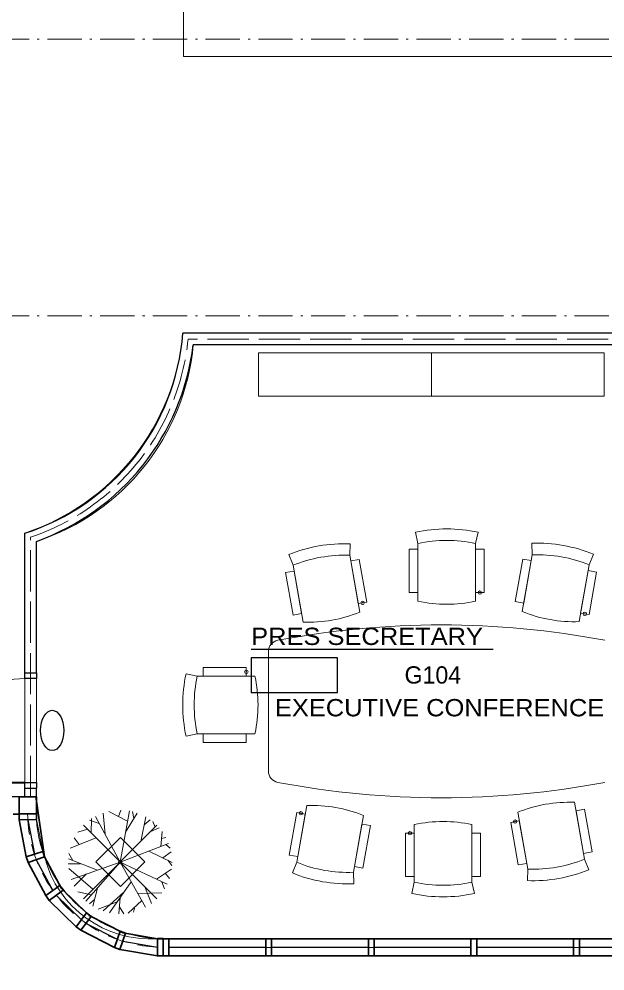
# Model space of a CAD drawing. Extents: x -118748 to -117136, y -118748 to -117596.
# Drawn here: x -117888.7 to -117726.1, y -118597 to -118332.8 of the extents above; entities that cross this region are included whole.
import ezdxf
from ezdxf.enums import TextEntityAlignment as Align

# ---------------------------------------------------------------- set-up
doc = ezdxf.new("R2010")
doc.units = 0
doc.header["$LTSCALE"] = 1.9
doc.header["$PDMODE"] = 32
doc.header["$PDSIZE"] = 0.95
for name, pattern in [('DOT_DASHED', [7.7, 5, -1.2, 0.3, -1.2]), ('LONG_DASHED', [7.5, 6, -1.5]), ('MEDIUM_DASHED', [4.5, 3, -1.5])]:
    doc.linetypes.add(name, pattern=pattern)
for name, color, linetype, lineweight in [('10', 7, 'DOT_DASHED', 13), ('15', 7, 'Continuous', 13), ('17', 7, 'Continuous', 25), ('2', 7, 'Continuous', 35), ('23', 7, 'Continuous', 25), ('25', 7, 'Continuous', 13), ('26', 7, 'Continuous', 25), ('3', 7, 'Continuous', 35), ('30', 7, 'Continuous', 13), ('4', 7, 'Continuous', 35), ('42', 7, 'Continuous', 25), ('45', 7, 'Continuous', 25), ('5', 7, 'Continuous', 13), ('6', 7, 'Continuous', 13), ('60', 7, 'LONG_DASHED', 13), ('8', 7, 'MEDIUM_DASHED', 13), ('9', 7, 'Continuous', 35)]:
    doc.layers.add(name, color=color, linetype=linetype, lineweight=lineweight)
doc.layers.add('53', color=7, linetype='Continuous')

msp = doc.modelspace()

# ---------------------------------------------------------------- linework, layer by layer
at = {"layer": '10'}
for p, q in [((-118641.571, -118338.41), (-117285.521, -118338.41)), ((-118641.571, -118415.21), (-117285.521, -118415.21))]:
    msp.add_line(p, q, dxfattribs=at)
at = {"layer": '15'}
for p, q in [((-117778.001, -118478.357), (-117778.677, -118475.23)), ((-117762.001, -118478.357), (-117761.325, -118475.23)), ((-117796.908, -118481.624), (-117796.786, -118478.427)), ((-117778.001, -118494.357), (-117778.001, -118478.357)), ((-117762.001, -118494.357), (-117762.001, -118478.357)), ((-117746.253, -118481.492), (-117746.376, -118478.294)), ((-117812.665, -118484.403), (-117813.874, -118481.44)), ((-117794.13, -118497.381), (-117796.908, -118481.624)), ((-117780.401, -118491.957), (-117780.401, -118479.957)), ((-117778.001, -118479.957), (-117780.401, -118479.957)), ((-117778.001, -118491.957), (-117778.001, -118479.957)), ((-117762.001, -118491.957), (-117762.001, -118479.957)), ((-117759.601, -118479.957), (-117762.001, -118479.957)), ((-117759.601, -118491.957), (-117759.601, -118479.957)), ((-117749.031, -118497.249), (-117746.253, -118481.492)), ((-117730.496, -118484.27), (-117729.287, -118481.307)), ((-117794.267, -118482.783), (-117796.63, -118483.2)), ((-117794.547, -118495.018), (-117796.63, -118483.2)), ((-117792.183, -118494.601), (-117794.267, -118482.783)), ((-117750.978, -118494.469), (-117748.894, -118482.651)), ((-117746.531, -118483.068), (-117748.894, -118482.651)), ((-117748.615, -118494.885), (-117746.531, -118483.068)), ((-117733.274, -118500.027), (-117730.496, -118484.27)), ((-117812.387, -118485.978), (-117814.751, -118486.395)), ((-117812.667, -118498.213), (-117814.751, -118486.395)), ((-117809.887, -118500.16), (-117812.665, -118484.403)), ((-117810.304, -118497.796), (-117812.387, -118485.978)), ((-117732.858, -118497.664), (-117730.774, -118485.846)), ((-117728.41, -118486.263), (-117730.774, -118485.846)), ((-117730.494, -118498.08), (-117728.41, -118486.263)), ((-117780.401, -118491.957), (-117778.001, -118491.957)), ((-117762.001, -118491.957), (-117759.601, -118491.957)), ((-117794.547, -118495.018), (-117792.183, -118494.601)), ((-117750.978, -118494.469), (-117748.615, -118494.885)), ((-117812.667, -118498.213), (-117810.304, -118497.796)), ((-117732.858, -118497.664), (-117730.494, -118498.08)), ((-117819.492, -118541.486), (-117819.492, -118508.352)), ((-117825.635, -118512.747), (-117837.635, -118512.747)), ((-117837.635, -118512.747), (-117837.635, -118515.147)), ((-117825.635, -118515.147), (-117825.635, -118512.747)), ((-117839.235, -118515.147), (-117842.362, -118514.47)), ((-117823.235, -118515.147), (-117839.235, -118515.147)), ((-117825.635, -118515.147), (-117837.635, -118515.147)), ((-117839.235, -118531.147), (-117842.362, -118531.823)), ((-117823.235, -118531.147), (-117839.235, -118531.147)), ((-117825.635, -118531.147), (-117837.635, -118531.147)), ((-117837.635, -118531.147), (-117837.635, -118533.547)), ((-117825.635, -118533.547), (-117825.635, -118531.147)), ((-117825.635, -118533.547), (-117837.635, -118533.547)), ((-117734.527, -118550.167), (-117731.748, -118565.924)), ((-117811.652, -118553.002), (-117813.735, -118564.82)), ((-117809.288, -118553.418), (-117811.652, -118553.002)), ((-117808.871, -118551.055), (-117811.65, -118566.812)), ((-117750.284, -118552.945), (-117747.505, -118568.702)), ((-117731.747, -118552.113), (-117734.11, -118552.53)), ((-117734.11, -118552.53), (-117732.026, -118564.348)), ((-117731.747, -118552.113), (-117729.663, -118563.931)), ((-117809.288, -118553.418), (-117811.372, -118565.236)), ((-117793.114, -118553.833), (-117795.893, -118569.59)), ((-117749.867, -118555.308), (-117752.231, -118555.725)), ((-117749.867, -118555.308), (-117747.783, -118567.126)), ((-117793.531, -118556.197), (-117795.615, -118568.015)), ((-117791.168, -118556.614), (-117793.531, -118556.197)), ((-117791.168, -118556.614), (-117793.251, -118568.431)), ((-117779.011, -118556.347), (-117779.011, -118572.347)), ((-117763.011, -118556.347), (-117763.011, -118572.347)), ((-117752.231, -118555.725), (-117750.147, -118567.543)), ((-117781.411, -118558.747), (-117781.411, -118570.747)), ((-117779.011, -118558.747), (-117781.411, -118558.747)), ((-117779.011, -118558.747), (-117779.011, -118570.747)), ((-117763.011, -118558.747), (-117763.011, -118570.747)), ((-117760.611, -118558.747), (-117763.011, -118558.747)), ((-117760.611, -118558.747), (-117760.611, -118570.747)), ((-117813.735, -118564.82), (-117811.372, -118565.236)), ((-117732.026, -118564.348), (-117729.663, -118563.931)), ((-117731.748, -118565.924), (-117730.539, -118568.886)), ((-117811.65, -118566.812), (-117812.859, -118569.775)), ((-117795.615, -118568.015), (-117793.251, -118568.431)), ((-117750.147, -118567.543), (-117747.783, -118567.126)), ((-117747.505, -118568.702), (-117747.628, -118571.899)), ((-117795.893, -118569.59), (-117795.77, -118572.788)), ((-117781.411, -118570.747), (-117779.011, -118570.747)), ((-117763.011, -118570.747), (-117760.611, -118570.747)), ((-117779.011, -118572.347), (-117779.687, -118575.475)), ((-117763.011, -118572.347), (-117762.334, -118575.475))]:
    msp.add_line(p, q, dxfattribs=at)
for points in [[(-117774.28, -118425.478), (-117774.28, -118437.478), (-117822.28, -118437.478), (-117822.28, -118425.478)], [(-117726.28, -118425.478), (-117726.28, -118437.478), (-117774.28, -118437.478), (-117774.28, -118425.478)]]:
    msp.add_lwpolyline(points, close=True, dxfattribs=at)
for centre, radius, start, end in [((-117770.001, -118515.366), 41.063, 77.80217, 102.19783), ((-117798.36, -118519.46), 41.063, 87.80217, 112.19782), ((-117770.001, -118515.366), 37.863, 77.80217, 102.19783), ((-117770.001, -118515.366), 37.863, 77.80217, 102.19783), ((-117744.801, -118519.327), 41.063, 67.80217, 92.19783), ((-117798.36, -118519.46), 37.863, 87.80217, 112.19782), ((-117798.36, -118519.46), 37.863, 87.80217, 112.19782), ((-117744.801, -118519.327), 37.863, 67.80217, 92.19783), ((-117744.801, -118519.327), 37.863, 67.80217, 92.19783), ((-117770.001, -118457.349), 37.863, 257.80217, 282.19783), ((-117808.435, -118462.324), 37.863, 267.80217, 292.19782), ((-117734.727, -118462.192), 37.863, 247.80217, 272.19783), ((-117771.492, -118743.319), 242.4, 79.20527, 100.79473), ((-117816.292, -118508.351), 3.2, 100.79473, 180), ((-117802.226, -118523.147), 41.063, 167.80217, 192.19782), ((-117802.226, -118523.147), 37.863, 167.80217, 192.19782), ((-117802.226, -118523.147), 37.863, 167.80217, 192.19782), ((-117860.243, -118523.147), 37.863, 347.80217, 12.19783), ((-117816.292, -118541.486), 3.2, 180, 259.20527), ((-117771.492, -118306.519), 242.4, 259.20527, 280.79473), ((-117735.979, -118588.002), 37.863, 87.80216, 112.19782), ((-117807.419, -118588.89), 37.863, 67.80217, 92.19782), ((-117771.011, -118593.355), 37.863, 77.80217, 102.19783), ((-117746.053, -118530.867), 37.863, 267.80217, 292.19783), ((-117746.053, -118530.867), 37.863, 267.80217, 292.19783), ((-117797.345, -118531.755), 37.863, 247.80217, 272.19783), ((-117797.345, -118531.755), 37.863, 247.80217, 272.19783), ((-117797.345, -118531.755), 41.063, 247.80217, 272.19783), ((-117746.053, -118530.867), 41.063, 267.80217, 292.19783), ((-117771.011, -118535.339), 37.863, 257.80217, 282.19783), ((-117771.011, -118535.339), 37.863, 257.80217, 282.19783), ((-117771.011, -118535.339), 41.063, 257.80217, 282.19783)]:
    msp.add_arc(centre, radius, start, end, dxfattribs=at)
for p in [(-117760.801, -118491.957), (-117793.365, -118494.809), (-117731.676, -118497.872), (-117825.635, -118513.947), (-117810.47, -118553.21), (-117751.049, -118555.517), (-117780.211, -118558.747)]:
    msp.add_point(p, dxfattribs=at)
at = {"layer": '17'}
msp.add_line((-117824.295, -118507.709), (-117757.095, -118507.709), dxfattribs=at)
at = {"layer": '2'}
msp.add_lwpolyline([(-117888.716, -118548.633), (-117888.716, -118553.358), (-117883.908, -118553.358), (-117883.908, -118548.633)], close=True, dxfattribs=at)
at = {"layer": '23'}
for p, q in [((-117698.321, -118420.01), (-117843.25, -118420.01)), ((-117698.321, -118423.21), (-117840.35, -118423.21)), ((-117887.108, -118514.233), (-117887.108, -118475.475)), ((-117883.908, -118514.233), (-117883.908, -118477.77)), ((-117887.108, -118514.233), (-117883.908, -118514.233)), ((-117887.108, -118546.233), (-117883.908, -118546.233)), ((-117887.108, -118548.633), (-117887.108, -118546.233)), ((-117883.908, -118548.633), (-117883.908, -118546.233)), ((-117887.108, -118548.633), (-117883.908, -118548.633))]:
    msp.add_line(p, q, dxfattribs=at)
for radius, start, end in [(63.254, 287.68267, 355.64793), (66.454, 289.71078, 353.08572)]:
    msp.add_arc((-117906.321, -118415.21), radius, start, end, dxfattribs=at)
at = {"layer": '25', "lineweight": 40}
msp.add_line((-117915.908, -118544.633), (-117887.108, -118544.633), dxfattribs=at)
at = {"layer": '25'}
msp.add_arc((-117887.108, -118544.633), 28.8, 90.00001, 180, dxfattribs=at)
at = {"layer": '26'}
for points in [[(-117883.908, -118514.233), (-117883.908, -118515.833), (-117887.108, -118515.833), (-117887.108, -118514.233)], [(-117887.108, -118546.233), (-117887.108, -118544.633), (-117883.908, -118544.633), (-117883.908, -118546.233)]]:
    msp.add_lwpolyline(points, dxfattribs=at)
at = {"layer": '3'}
msp.add_lwpolyline([(-118098.321, -117954.41), (-117829.521, -117954.41), (-117459.921, -117954.41), (-117459.921, -118170.41), (-117370.321, -118170.41), (-117370.321, -118352.81), (-117459.921, -118352.81), (-117459.921, -118645.61), (-117704.721, -118645.61), (-117704.721, -118592.81), (-117847.121, -118592.81), (-117850.321, -118592.801), (-117860.744, -118590.984), (-117862.249, -118590.443), (-117871.571, -118585.668), (-117872.847, -118584.703), (-117880.323, -118577.368), (-117881.254, -118576.067), (-117886.205, -118566.837), (-117886.706, -118565.318), (-117888.682, -118555.032), (-117888.707, -118553.433), (-117890.316, -118553.433)], dxfattribs=at)
at = {"layer": '30'}
for p, q in [((-117858.58, -118555.405), (-117863.781, -118552.673)), ((-117861.071, -118554.096), (-117860.479, -118552.331)), ((-117860.655, -118566.73), (-117858.059, -118552.566)), ((-117856.841, -118554.677), (-117857.251, -118552.738)), ((-117866.438, -118556.086), (-117869.12, -118555.081)), ((-117868.718, -118558.667), (-117868.571, -118554.701)), ((-117860.655, -118566.73), (-117867.529, -118554.077)), ((-117864.852, -118559.004), (-117865.392, -118553.132)), ((-117859.135, -118558.439), (-117855.901, -118553.137)), ((-117854.95, -118561.025), (-117853.513, -118554.226)), ((-117853.975, -118556.41), (-117852.309, -118554.995)), ((-117850.944, -118557.019), (-117851.6, -118555.533)), ((-117869.732, -118557.653), (-117872.414, -118558.418)), ((-117850.472, -118556.548), (-117870.837, -118576.912)), ((-117850.472, -118576.912), (-117870.837, -118556.548)), ((-117852.161, -118558.236), (-117849.832, -118557.231)), ((-117849.332, -118562.428), (-117848.988, -118558.289)), ((-117867.323, -118560.061), (-117874.535, -118562.897)), ((-117871.991, -118561.897), (-117873.4, -118560.027)), ((-117849.148, -118560.215), (-117847.965, -118559.924)), ((-117860.655, -118566.73), (-117847.194, -118561.615)), ((-117847.99, -118561.918), (-117846.764, -118562.932)), ((-117866.978, -118568.978), (-117875.029, -118565.875)), ((-117873.789, -118566.353), (-117874.857, -118564.35)), ((-117852.724, -118563.717), (-117846.255, -118566.831)), ((-117848.805, -118565.603), (-117846.53, -118563.925)), ((-117871.607, -118567.194), (-117875.044, -118567.284)), ((-117868.236, -118574.311), (-117874.936, -118568.573)), ((-117860.655, -118566.73), (-117874.223, -118571.554)), ((-117860.655, -118566.73), (-117870.13, -118577.573)), ((-117860.655, -118566.73), (-117853.609, -118579.289)), ((-117860.655, -118566.73), (-117847.622, -118572.855)), ((-117850.602, -118571.455), (-117846.391, -118568.709)), ((-117847.429, -118566.266), (-117846.285, -118567.668)), ((-117869.982, -118570.046), (-117873.387, -118573.456)), ((-117848.172, -118569.87), (-117846.994, -118571.284)), ((-117866.977, -118573.965), (-117868.245, -118578.967)), ((-117857.566, -118572.236), (-117863.641, -118580.817)), ((-117853.809, -118573.576), (-117851.986, -118578.229)), ((-117849.043, -118572.187), (-117848.325, -118574.168)), ((-117868.577, -118575.797), (-117872.427, -118575.022)), ((-117859.597, -118575.105), (-117865.406, -118580.323)), ((-117860.667, -118576.617), (-117860.993, -118581.126)), ((-117855.755, -118575.463), (-117849.07, -118575.283)), ((-117867.784, -118577.149), (-117869.199, -118578.321)), ((-117861.505, -118577.8), (-117866.704, -118579.798)), ((-117860.851, -118579.163), (-117859.663, -118581.096)), ((-117854.654, -118577.427), (-117858.446, -118580.959)), ((-117856.554, -118579.197), (-117856.955, -118580.647))]:
    msp.add_line(p, q, dxfattribs=at)
msp.add_lwpolyline([(-117853.802, -118566.727), (-117860.59, -118573.515), (-117867.378, -118566.727), (-117860.59, -118559.938)], close=True, dxfattribs=at)
msp.add_point((-117860.655, -118566.73), dxfattribs=at)
at = {"layer": '4'}
msp.add_lwpolyline([(-118496.721, -117964.01), (-118496.721, -118636.01), (-118271.121, -118636.01), (-118271.121, -118588.01), (-118115.969, -118588.01), (-118106.1, -118586.234), (-118096.66, -118581.314), (-118089.115, -118573.804), (-118084.156, -118564.399), (-118081.154, -118548.633), (-118079.134, -118548.633), (-117884.057, -118548.587), (-117881.646, -118565.336), (-117876.897, -118574.111), (-117869.271, -118581.538), (-117859.789, -118586.351), (-117850.271, -118588.01), (-117695.121, -118588.01), (-117695.121, -118636.01), (-117469.521, -118636.01), (-117469.521, -117964.01)], close=True, dxfattribs=at)
at = {"layer": '42'}
msp.add_ellipse((-117879.508, -118530.233), major_axis=(0, -5.6), ratio=0.571429, dxfattribs=at)
at = {"layer": '45'}
msp.add_lwpolyline([(-117824.295, -118510.109), (-117824.295, -118519.709), (-117800.295, -118519.709), (-117800.295, -118510.109)], close=True, dxfattribs=at)
at = {"layer": '5'}
for points in [[(-117979.078, -117964.01), (-117469.521, -117964.01), (-117469.521, -118636.01), (-117695.121, -118636.01), (-117695.121, -118588.01), (-117850.271, -118588.01)], [(-117843.071, -118184.81), (-117843.071, -118295.21), (-117503.121, -118295.21), (-117469.521, -118295.21), (-117469.521, -118301.61), (-117469.521, -118343.21), (-117479.121, -118343.21), (-117698.321, -118343.21), (-117698.321, -118357.61), (-117698.321, -118420.01), (-117843.25, -118420.01)], [(-117840.35, -118423.21), (-117666.321, -118423.21), (-117666.321, -118456.81), (-117666.321, -118588.01), (-117706.321, -118588.01), (-117847.121, -118588.01), (-117850.321, -118588.001), (-117859.12, -118586.467), (-117860.626, -118585.926), (-117868.676, -118581.84), (-117869.952, -118580.875), (-117876.419, -118574.577), (-117877.349, -118573.275), (-117881.646, -118565.336), (-117882.147, -118563.816), (-117883.883, -118554.958), (-117883.908, -118477.769)], [(-117887.108, -118475.475), (-117887.108, -118548.633), (-118079.134, -118548.633), (-118079.133, -118475.475)], [(-117881.646, -118565.336), (-117884.057, -118548.587), (-118079.134, -118548.633), (-118081.154, -118548.633), (-118084.156, -118564.399)]]:
    msp.add_lwpolyline(points, dxfattribs=at)
for centre, radius, start, end in [((-117906.321, -118415.21), 63.254, 287.68267, 355.64793), ((-117906.321, -118415.21), 66.454, 289.71078, 353.08572), ((-117852.266, -118557.725), 30.35, 194.52311, 273.7691)]:
    msp.add_arc(centre, radius, start, end, dxfattribs=at)
at = {"layer": '6'}
msp.add_line((-117883.908, -118477.77), (-117883.883, -118554.958), dxfattribs=at)
for points in [[(-117843.071, -118184.81), (-117843.071, -118343.21), (-117698.321, -118343.21), (-117698.321, -118420.01), (-117843.25, -118420.01)], [(-117850.321, -118588.001), (-117695.121, -118588.01), (-117695.121, -118636.01), (-117469.521, -118636.01), (-117469.521, -118423.21), (-117840.35, -118423.21)], [(-117887.108, -118475.475), (-117887.108, -118548.633), (-118079.134, -118548.633), (-118079.134, -118475.475)]]:
    msp.add_lwpolyline(points, dxfattribs=at)
msp.add_lwpolyline([(-117843.071, -118295.21), (-117469.521, -118295.21), (-117469.521, -118343.21), (-117843.071, -118343.21)], close=True, dxfattribs=at)
for centre, radius, start, end in [((-117907.46, -118414.309), 64.463, 288.40401, 354.92664), ((-117903.662, -118417.332), 63.584, 288.09981, 354.69642), ((-117848.402, -118552.486), 35.567, 183.98479, 266.90793)]:
    msp.add_arc(centre, radius, start, end, dxfattribs=at)
at = {"layer": '60'}
for p, q in [((-117696.721, -118421.61), (-117841.784, -118421.61)), ((-117885.508, -118548.633), (-117885.508, -118476.633))]:
    msp.add_line(p, q, dxfattribs=at)
msp.add_arc((-117906.321, -118415.21), 64.854, 288.71868, 354.33663, dxfattribs=at)
at = {"layer": '8'}
msp.add_line((-117704.721, -118590.41), (-117848.721, -118590.41), dxfattribs=at)
msp.add_arc((-117848.721, -118552.81), 37.6, 180.89285, 270.00018, dxfattribs=at)
at = {"layer": '9', "lineweight": 13}
for p, q in [((-117888.682, -118555.032), (-117886.706, -118565.318)), ((-117883.883, -118554.958), (-117882.147, -118563.816)), ((-117881.646, -118565.336), (-117877.349, -118573.275)), ((-117886.205, -118566.837), (-117881.254, -118576.067)), ((-117876.419, -118574.577), (-117869.952, -118580.875)), ((-117880.323, -118577.368), (-117872.847, -118584.703)), ((-117868.676, -118581.84), (-117860.626, -118585.926)), ((-117871.571, -118585.668), (-117862.249, -118590.443)), ((-117859.12, -118586.467), (-117850.321, -118588.001)), ((-117706.321, -118588.01), (-117847.121, -118588.01)), ((-117860.744, -118590.984), (-117850.321, -118592.801)), ((-117706.321, -118592.81), (-117847.121, -118592.81))]:
    msp.add_line(p, q, dxfattribs=at)
at = {"layer": '9', "lineweight": 25}
for p, q in [((-117886.283, -118554.995), (-117884.426, -118564.567)), ((-117883.926, -118566.087), (-117879.302, -118574.671)), ((-117878.371, -118575.973), (-117871.399, -118582.789)), ((-117870.123, -118583.755), (-117861.438, -118588.185)), ((-117859.932, -118588.726), (-117850.321, -118590.401)), ((-117820.241, -118590.41), (-117847.121, -118590.41)), ((-117791.761, -118590.41), (-117818.641, -118590.41)), ((-117763.281, -118590.41), (-117790.161, -118590.41)), ((-117734.801, -118590.41), (-117761.681, -118590.41)), ((-117706.321, -118590.41), (-117733.201, -118590.41))]:
    msp.add_line(p, q, dxfattribs=at)
at = {"layer": '9'}
for points in [[(-117883.883, -118554.958), (-117883.908, -118553.358), (-117888.707, -118553.433), (-117888.682, -118555.032)], [(-117881.646, -118565.336), (-117882.147, -118563.816), (-117886.706, -118565.318), (-117886.205, -118566.837)], [(-117876.419, -118574.577), (-117877.349, -118573.275), (-117881.254, -118576.067), (-117880.323, -118577.368)], [(-117868.676, -118581.84), (-117869.952, -118580.875), (-117872.847, -118584.703), (-117871.571, -118585.668)], [(-117859.12, -118586.467), (-117860.626, -118585.926), (-117862.249, -118590.443), (-117860.744, -118590.984)], [(-117848.721, -118588.001), (-117850.321, -118588.001), (-117850.321, -118592.801), (-117848.721, -118592.801)], [(-117848.721, -118592.81), (-117847.121, -118592.81), (-117847.121, -118588.01), (-117848.721, -118588.01)], [(-117820.241, -118592.81), (-117818.641, -118592.81), (-117818.641, -118588.01), (-117820.241, -118588.01)], [(-117791.761, -118592.81), (-117790.161, -118592.81), (-117790.161, -118588.01), (-117791.761, -118588.01)], [(-117763.281, -118592.81), (-117761.681, -118592.81), (-117761.681, -118588.01), (-117763.281, -118588.01)], [(-117734.801, -118592.81), (-117733.201, -118592.81), (-117733.201, -118588.01), (-117734.801, -118588.01)]]:
    msp.add_lwpolyline(points, close=True, dxfattribs=at)

# ---------------------------------------------------------------- texts
at = {"layer": '17', "width": 1.1}
msp.add_text('PRES SECRETARY', height=4.8, dxfattribs=at).set_placement((-117824.295, -118506.509))
at = {"layer": '53', "width": 1.1}
msp.add_text('EXECUTIVE CONFERENCE', height=4.8, dxfattribs=at).set_placement((-117817.7, -118526.309))
at = {"layer": '9'}
msp.add_text('G104', height=4.8, dxfattribs=at).set_placement((-117773.862, -118517.22), align=Align.CENTER)

doc.saveas('drawing.dxf')
